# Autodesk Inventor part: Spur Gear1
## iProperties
Created: 2008-01
Part Number: Spur Gear1
Material: Steel
Document SubType Name: Modeling
Designer: eruiz-tagle
Mass: 0.924245 g
Surface Area: 2.83839 cm^2
Volume: 0.117738 cm^3
Density: 7.85 g/cm^3
CustomPartVersion: 1
Author: eruiz-tagle
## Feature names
1. Extrusion1
